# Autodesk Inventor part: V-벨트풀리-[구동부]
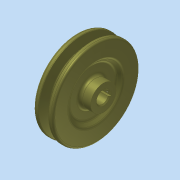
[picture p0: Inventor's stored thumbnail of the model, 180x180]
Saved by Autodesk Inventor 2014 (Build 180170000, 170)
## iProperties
Company: 한국ATC센터
Created: 2014-02
Part Number: V-벨트풀리-[구동부]
Document SubType Name: Modeling
Designer: KYOUNG IL JANG
Density: 7.25 g/cm^3
Mass: 594.643 g
Surface Area: 210.328 cm^2
Volume: 82.0197 cm^3
Material: 주철
Vendor: CBT Solutions
Appearance: 티타늄
Author: KYOUNG IL JANG
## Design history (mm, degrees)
sketch "스케치1"
  geometry: L1 (-13, 0)-(13, 0); L2 (-13, 0)-(-13, 12.5); L3 (-13, 12.5)-(-9, 12.5); L4 (-9, 12.5)-(-9, 23); L5 (-9, 23)-(-13, 27); L6 (-13, 27)-(-13, 42.7); L7 (-13, 42.7)-(-8.325, 42.7); L8 (-8.325, 42.7)-(-5.574, 33.7); L9 (-5.574, 33.7)-(-1.426, 33.7); L10 (-1.426, 33.7)-(1.325, 42.7); L11 (1.325, 42.7)-(6, 42.7); L12 (6, 42.7)-(6, 27); L13 (6, 27)-(2, 23); L14 (2, 23)-(2, 12.5); L15 (2, 12.5)-(13, 12.5); L16 (13, 12.5)-(13, 0); L17 (-7.5, 40)-(0.5, 40); 2 further points
  constraints: 34 end point, 6 parallel, 5 collinear, 5 equal length, 4 perpendicular, 2 point on line, 1 coincident, 1 horizontal, 1 midpoint
  dimensions: "d0" = 26 distance of L1.start L1.end; "d1" = 2.7 distance between parallel lines of L7 L17; "d2" = 6.3 distance between parallel lines of L9 L17; "d3" = 8 distance of L17.start L17.end; "d4" = 34 deg angle of L10 L8; "d5" = 19 distance between parallel lines of L12 L6; "d7" = 25 diameter of L15 L1; "d8" = 46 diameter of L13.end L1; "d9" = 54 diameter of L12.end L1; "d10" = 4 distance between parallel lines of L2 L4; "d11" = 80 diameter of L17 L1
revolve "회전1" sketch "스케치1" stored, may be unused: angle "d12" = 90 deg
sketch "스케치2"
  geometry: L1 (-2, 5.657)-(-2, 7.8); L2 (-2, 7.8)-(2, 7.8); L3 (2, 7.8)-(2, 5.657); A1 r 6 centre (0, 0) between (-2, 5.657) and (2, 5.657); 1 further point
  constraints: 6 end point, 2 parallel, 2 point on circle, 1 centre point, 1 coincident, 1 perpendicular, 1 vertical
  dimensions: "d13" = 12 diameter of A1; "d14" = 13.8 dimension on A1 L2; "d15" = 4 distance of L1.end L2.end
extrude "돌출1" cut sketch "스케치2" stored distance "d16" = 10; taper "d17" = 0 deg
node "작업 평면1"
sketch "스케치3"
  geometry: L1 (-5.5, 12.5)-(-5.5, -12.5) reference; 3 further points
  constraints: 1 horizontal alignment, 1 midpoint
  dimensions: "d18" = 4 distance from line of point (-1.5, 0) L1
hole "구멍1" sketch "스케치3" at (-1.5, 0) diameter "d19" = 2.459; stored, may be unused: countersink angle "d23" = 90 deg, drill point angle "d25" = 118 deg; dims "d20" = 6, "d21" = 4, "d22" = 2, "d24" = 8
fillet "모깎기1" dims "d26" = 2, "d27" = 0.5, "d28" = 1, "d29" = 3
chamfer "모따기1" distance "d30" = 1; stored, may be unused: second distance "d31" = 2, angle "d32" = 45 deg
node "솔리드1"
